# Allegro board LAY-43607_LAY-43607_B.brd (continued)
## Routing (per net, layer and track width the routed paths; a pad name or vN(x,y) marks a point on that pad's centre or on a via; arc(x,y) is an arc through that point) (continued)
AVDD_SRDS1_PLL1: length 0.6
  TOP w0.381: U14.AA11 v1(59.03,48.59)
  vias: v4(49.52,50.18) v4(50.28,49.93)
AVDD_SRDS1_PLL2: length 0.6
  TOP w0.381: U14.AB6 v1(58.22,52.6)
  vias: v4(49.64,54.63)
AVDD_SRDS2_PLL1: length 0.6
  TOP w0.381: U14.AB15 v1(59.02,45.39)
  vias: v4(46.34,47.77) v4(47.58,48.25) v4(49.79,47.9)
AVDD_SRDS2_PLL2: length 0.6
  TOP w0.137: U14.AA16 59.42,44.19
  TOP w0.381: 59.42,44.19 v1(59.02,43.79)
  vias: v4(46.19,43.48) v4(48.25,43.5) v4(49.01,43.45)
GND: length 689.8
  TOP w0.094: 36.21,73.66 36.62,74.07 36.8,74.07 37.2,73.67 U123.D9
  TOP w0.203: U38.2 75.88,109.42 ; U39.2 80.71,109.44
  TOP w0.254: U563.2 127.92,13.47 128.05,13.61 v2(128.1,13.61) ; v4(67.68,72.55) 68.1,72.97 U561.16 ; U540.4 84.78,99.74 v2(84.62,99.58) ; 110.88,92.27 U40.B3 U40.C3 ; J52.75 33.89,41.23 v4(33.84,41.18) ; J52.63 v4(30.89,41.18) ; U40.C3 U40.D3 110.87,93.07 ; U40.C3 110.86,92.67 ; U35.4 72.9,99.92 v2(72.55,99.57) ; R933.2 v4(69.07,85.49) ; U561.51 70.1,82.2 v4(70.21,82.31) ; v7(70.86,79.09) 70.86,79.99 71.6,80.73 U561.48 ; U550.C3 U550.B3 104.17,91.97 ; U550.C3 104.15,92.37 ; U550.C3 U550.D3 104.17,92.77 ; U540.5 84.78,98.33 84.59,98.52 v2(84.59,98.87) ; U37.4 77.19,98.3 v2(77.56,98.67) ; v2(127.24,55.26) 126.99,55.51 U558.7 ; U539.4 78.69,99.88 78.5,99.69 78.5,99.59 v2(78.41,99.51) ; U558.2 129.53,54.51 v2(129.4,54.37) 129.76,54.01 U558.1 ; U561.43 74.1,81.75 v4(74.55,82.2) ; v2(72.63,98.6) 72.9,98.33 U35.5 ; U539.5 78.69,98.24 78.42,98.51 v2(78.42,98.7) ; J52.69 v4(32.39,41.18) ; U561.45 v4(73.1,82.61) ; J52.57 v4(29.39,41.18) ; v7(70.8,76) 70.8,75.61 69.6,74.41 U561.19 ; J52.45 v4(26.39,41.18) ; U525.8 v4(92.16,85.76) ; U561.12 66.02,75.26 65.75,74.99 v4(64.92,74.99) ; J52.51 v4(27.89,41.16) ; R932.2 v4(69.96,85.44) ; C1546.2 v4(72.25,85.01) ; U1.14 v4(115.71,83.33) ; J52.18 v4(19.64,36.11) ; v2(77.51,99.56) 77.49,99.56 77.19,99.86 U37.5
  TOP w0.305: J52.39 v4(24.89,41.22) ; R841.1 v4(116.83,13.81) ; C1317.2 84.21,112.36 83.91,112.06 83.91,111.96 v4(83.79,111.84) 84.21,111.42 C1316.2 ; U551.3 v2(104.58,85.98) ; U548.2 v2(88.43,111.63) ; U536.3 121.3,10.63 v1(121.55,10.88) ; v2(81.49,98.59) 81.79,98.3 U36.5 ; U536.12 122.3,12.58 121.89,12.17 v1(121.55,12.17) ; U36.4 81.79,99.77 v2(81.56,99.54) ; v2(76.69,101.64) U37.6 ; U552.1 v2(97.43,99.93) ; J52.33 v4(23.39,41.2)
  TOP w0.381: U14.N26 65.82,36.2 v2(66.22,35.8) ; v2(74.22,56.6) U14.C1 ; U14.K15 68.22,45 v1(68.62,44.6) ; U14.C5 v1(74.62,53.8) U14.A4 ; U14.AG21 v2(55.02,40.6) 54.62,41 U14.AG20 U14.AH20 ; U14.AF10 55.42,49 v2(55.02,48.6) ; U14.J26 69.02,36.2 v2(69.42,35.8) ; U14.T11 v1(63.03,48.59) U14.U10 v1(62.23,49.39) 61.82,49.8 U14.V9 v1(61.43,50.19) ; U14.Y16 v1(59.82,44.59) ; v3(73.43,50.19) 73.03,49.8 U14.D9 ; v1(67.83,39.8) 68.22,40.2 U14.K21 ; U14.T23 63.42,38.6 v1(63.03,38.2) ; v2(59.83,35.8) 60.22,36.2 U14.Y26 ; U14.AB9 v2(59.02,49.4) ; U14.AD7 v1(56.62,51.8) ; U14.AA7 v2(59.02,51.8) ; U14.F3 v1(72.22,55.4) U14.E2 ; U14.H24 69.82,37.8 v2(70.22,37.4) ; v2(66.22,54.2) U14.N4 ; v2(72.63,39.8) 73.02,40.2 U14.D21 ; v2(56.62,37.4) 56.22,37.8 U14.AE24 ; C489.2 v4(121.54,19.94) ; v2(62.23,50.99) U14.U8 v1(63.03,50.19) U14.T9 63.42,49.79 v1(63.82,49.39) U14.R10 ; v2(62.22,39.8) 61.82,40.2 U14.V21 v2(61.42,39.79) U14.W22 ; U14.P13 v1(65.42,46.99) U14.N12 v1(66.22,47.79) U14.M11 v1(67.02,48.59) U14.L10 v2(67.82,49.39) ; U14.L20 67.42,41 v2(67.03,40.6) ; v2(75.99,40.2) U14.A21 ; U14.H14 69.83,45.8 v1(70.23,46.19) ; v1(62.23,38.2) 62.62,38.6 U14.U23 ; U14.AG26 54.62,36.2 v2(55.02,35.8) ; v2(59.82,38.19) U14.AA24 ; v2(63.03,35.8) 63.42,36.2 U14.T26 ; U14.R5 v1(63.83,53.39) ; U14.AH6 v2(53.42,51.8) ; v2(68.62,55.8) U14.K2 ; U14.AC5 v2(57.42,53.4) ; U14.V6 v1(61.43,52.59) ; v4(19.67,115.89) 19.97,115.59 C1151.2 ; U14.K6 68.62,52.6 v1(68.63,52.6) U14.J6 69.03,52.2 v2(69.43,51.79) 69.03,51.4 U14.J7 ; U14.AD21 v2(56.62,39.8) ; U14.M23 66.62,38.6 v1(67.02,38.2) ; U14.AH18 v2(53.42,43) U14.AH17 ; U14.AC18 v2(57.42,42.2) U14.AC19 ; U15.T1 88.79,6.11 88.69,6.21 88.1,6.21 v2(88.09,6.22) ; v2(56.63,54.19) U14.AD4 ; v1(69.43,48.59) 69.03,48.2 U14.J11 ; U14.H21 69.82,40.2 v2(69.43,39.8) ; v2(70.22,54.2) U14.H4 ; v3(73.43,47.79) 73.03,47.4 U14.D12 ; U14.P23 65.02,38.6 v1(65.42,38.2) ; v1(70.22,43.8) 69.82,44.2 U14.H16 ; v2(59.03,53.4) 59.42,53 U14.AA5 ; v2(74.23,39.8) 74.62,40.2 U14.B21 ; U14.P6 65.42,52.6 v1(65.43,52.6) ; U14.G26 70.62,36.2 v2(71.02,35.8) ; v2(59.82,45.39) U14.Y15 ; C1314.2 44.02,62.16 v4(43.71,61.85) ; v2(61.43,35.8) 61.82,36.2 U14.V26 ; U14.J23 69.02,38.6 v2(69.42,38.2) ; C1555.2 v4(118.21,28.5) ; U14.N20 65.82,41 v2(65.43,40.6) ; U14.R23 64.22,38.6 v1(63.83,38.2) ; v3(74.22,43.8) 74.62,44.2 U14.B16 ; U14.AC24 57.82,37.8 v2(58.22,37.4) ; v2(60.62,38.99) U14.Y23 ; U14.AE5 v2(55.82,53.4) ; v2(74.22,36.59) U14.B26 ; v2(72.62,35.8) 72.22,36.2 U14.E26 ; U14.N23 65.82,38.6 v1(66.22,38.2) ; FL8.2 v4(46.59,49.8) ; v2(55.82,36.59) U14.AF26 ; v1(60.63,42.2) 61.02,42.6 U14.W18 v1(61.43,43) 61.82,43.4 U14.V17 61.82,43.4 v1(62.23,43.8) 62.62,44.2 U14.U16 62.62,44.2 v1(63.03,44.6) 63.42,45 U14.T15 ; v1(68.62,46.99) U14.K13 v1(67.82,46.19) U14.L14 ; U14.AE7 v2(55.82,51.8) U14.AF7 ; U14.R12 v1(63.83,47.79) ; v2(70.22,53.4) U14.H5 ; v1(67.82,47.79) U14.L12 v1(67.02,46.99) U14.M13 v1(66.22,46.19) U14.N14 ; U14.AF8 v2(55.02,51) U14.AG8 v2(54.22,51) U14.AG7 ; U14.F16 71.42,44.19 v3(71.82,43.79) ; v2(74.23,41.4) 74.62,41.8 U14.B19 ; U14.AE17 v1(56.22,43.4) U14.AF18 v2(55.02,43) U14.AF17 U14.AF16 ; C492.2 v4(117.66,25.11) ; U14.AE14 v2(55.82,45.4) ; U14.AG14 v2(54.22,45.4) U14.AG15 ; v1(66.23,52.6) 66.22,52.6 U14.N6 ; v1(61.43,44.6) 61.82,45 U14.V15 ; U562.3 121.23,29.17 v4(121.22,29.17) ; U14.G9 70.63,49.8 v1(71.03,50.19) ; U14.AH9 v2(53.42,50.2) ; U14.AB26 58.62,36.2 v2(58.23,35.8) ; v1(60.62,40.6) U14.W20 v1(61.43,41.4) 61.82,41.8 U14.V19 61.82,41.8 v1(62.23,42.2) 62.62,42.6 U14.U18 62.62,42.6 v1(63.03,43) 63.42,43.4 U14.T17 v1(63.83,43.8) 64.22,44.2 U14.R16 ; U14.AG9 v2(54.22,50.2) ; U14.AH11 v2(53.42,47.8) U14.AH12 U14.AH13 U14.AG13 U14.AG12 v2(54.22,47.8) U14.AG11 ; v1(63.03,39.8) 63.42,40.2 U14.T21 v1(63.83,40.6) 64.22,41 U14.R20 ; v2(59.83,55.79) U14.Y2 ; v1(67.82,42.2) U14.K19 68.22,41.8 v2(67.83,41.4) ; U14.C2 v2(74.22,55.8) ; U14.B13 74.62,46.6 v3(74.22,46.2) ; v4(98.01,62.93) 98.01,62.94 98.39,63.32 U549.4 ; v2(59.83,51.8) 60.22,51.4 U14.Y7 ; v6(35.51,73.14) 35.83,73.46 36.01,73.46 36.21,73.66 ; v2(69.42,47.79) U14.J12 ; U14.AA19 v1(59.02,42.2) ; v2(75.96,55.4) U14.A2 ; v2(70.23,39.8) 70.62,40.2 U14.G21 ; v2(63.03,53.39) U14.T5 ; C1248.2 109.83,22.57 v3(109.03,21.77) 109.47,21.33 109.47,21.32 109.79,21 C1433.2 ; R662.2 C693.2 v5(43.39,87.27) ; v2(73.42,42.2) 73.02,42.6 U14.D18 ; U16.T1 v1(78.16,6.11) ; v2(56.63,35.8) 57.02,36.2 U14.AD26 ; v4(92.23,65.02) 91.84,65.41 U566.3 ; U14.C27 73.82,35.4 v1(74.22,35) ; U14.N8 v1(66.22,50.99) ; v2(73.43,39.8) 73.82,40.2 U14.C21 ; v1(67.83,52.6) 67.82,52.6 U14.L6 ; U14.AH5 v2(54.22,53.4) U14.AG5 ; U14.V23 61.82,38.6 v1(61.43,38.2) ; U14.AG6 v2(55.02,52.6) U14.AF6 ; U14.A3 v1(74.62,54.6) ; v1(67.02,50.19) U14.M9 v1(66.22,49.39) U14.N10 v1(65.42,48.59) U14.P11 ; U14.F7 71.43,51.4 v3(71.83,51.79) ; v1(68.62,49.4) 69.02,49 U14.J10 ; U14.P9 v1(65.42,50.19) ; v2(66.23,41.4) 66.62,41.8 U14.M19 v1(66.22,42.2) 65.82,42.6 U14.N18 v1(65.42,43) 65.02,43.4 U14.P17 ; v2(55.03,54.19) U14.AF4 ; U14.F4 71.77,53.45 U14.E5 U14.D4 v1(73.02,53.8) ; U14.AF9 v2(55.02,50.2) ; C284.2 v2(45.63,31.92) ; v2(59.02,50.2) U14.AA9 v1(59.82,49.39) U14.Y10 ; U14.U6 63.02,52.6 v1(63.03,52.6) U14.T6 ; v1(68.62,43) 68.22,43.4 U14.K17 v1(67.82,43.8) U14.L16 v1(67.02,44.6) 66.62,45 U14.M15 ; U14.AD12 v2(56.62,47.8) ; U14.Y14 v1(59.83,46.19) 59.82,46.19 U14.AA14 ; v1(60.62,47.79) U14.W12 61.02,47.39 v1(61.42,46.99) U14.V13 ; v2(71.83,39.8) 72.22,40.2 U14.E21 ; v2(56.63,55.79) U14.AD2 ; U14.AH14 v2(53.42,45.4) U14.AH15 ; U56.3 v4(121.07,26.41) ; U14.H18 69.82,42.6 v1(70.22,42.2) ; U14.AC10 v1(57.42,49.4) ; v1(59.02,47.8) U14.AA12 ; U530.3 100.01,87.72 100.6,87.14 v4(100.7,87.14) ; v2(64.96,30.22) 64.93,30.24 R141.1 ; U14.AC8 v2(58.22,50.2) ; v1(59.83,52.6) 60.22,52.2 U14.Y6 ; C1150.2 v5(42.78,110.76) ; U14.R14 v1(63.83,46.19) 63.42,46.6 U14.T13 v1(63.03,46.99) 62.62,47.4 U14.U12 v1(62.23,47.79) 61.82,48.2 U14.V11 v1(61.43,48.59) ; U14.U14 v1(62.22,46.19) ; U549.5 v4(101.09,63.32) ; U14.H17 69.82,43.4 v1(70.22,43) ; v2(54.22,56.6) U14.AG1 ; R185.2 v4(84.69,44.92) ; U14.AE9 v2(55.82,50.2) ; U14.U4 v1(62.23,54.19) ; U14.A5 76.11,53 v3(76.12,52.99) ; U14.M21 66.62,40.2 v2(66.23,39.8) ; U14.N2 v2(66.22,55.8) ; U14.B24 74.62,37.8 v2(75.02,37.4) ; v2(71.82,42.2) U14.F18 ; U14.AB14 v1(59.02,46.19) ; v2(71.03,49.39) 70.63,49 U14.G10 ; v3(75.03,49.39) 74.63,49 U14.B10 ; U14.H15 69.82,45 v1(70.22,44.6) ; v2(61.43,54.19) U14.V4 ; v5(129.22,41.93) R64.2 ; U14.AF15 v2(55.02,45.4) ; v2(63.03,54.19) U14.T4 ; R177.2 v4(85.46,44.79) ; U14.AC6 v1(57.42,52.6) ; C282.2 v2(45.6,27.17) ; U14.AG18 v2(54.22,43) U14.AG17 ; U14.Y21 v2(59.82,39.8) ; U14.AA18 v1(59.02,43) U14.AB17 ; U14.AB7 v2(58.22,51.8) ; v2(58.23,55.79) U14.AB2 ; v2(67.82,35.8) U14.L26 ; U14.P15 65.02,45 v1(65.42,44.6) U14.N16 65.82,44.2 v1(66.22,43.8) U14.M17 v1(67.02,43) U14.L18 ; U14.H3 v2(70.22,55) U14.G2 U14.G1 ; v2(53.43,55.79) U14.AH2 ; U14.Y13 v1(59.83,46.99) ; v2(63.83,35.8) 64.22,36.2 U14.R26 ; C1142.2 v5(65.82,115.46) ; v2(59.83,53.4) 60.22,53 U14.Y5 ; U14.AC11 v2(57.42,48.6) ; U14.L23 v1(67.82,38.2) ; v2(68.62,54.2) U14.K4 ; v2(63.82,55) U14.T2 ; U14.AA17 v1(59.82,43.79) ; U14.B7 74.63,51.4 v3(75.03,51.79) ; v1(58.22,47.8) U14.AB12 ; U14.AH21 v2(53.24,40.2) ; v1(64.63,41.4) 65.02,41.8 U14.P19 ; v1(71.03,48.59) 70.63,48.2 U14.G11 ; U14.AD14 v1(56.62,45.4) ; U14.R8 v1(63.83,50.99) ; v1(67.03,52.6) 67.02,52.6 U14.M6 ; U14.AC15 v2(58.22,45.4) ; v1(69.43,50.19) 69.03,49.8 U14.J9 ; U14.AA21 v1(59.02,39.8) ; U14.AD9 v2(56.62,50.2) ; U14.D24 73.02,37.8 v2(73.42,37.4) ; U14.AG24 54.62,37.8 v2(54.23,37.4) ; U14.AF21 v2(55.02,39.8) ; U14.AH7 v2(53.42,51) U14.AH8 ; U14.F14 71.43,45.8 v1(71.83,46.19) ; U14.D15 73.02,44.99 v3(73.42,44.59) ; U14.AD5 v2(56.62,53.4) ; U14.AC21 v1(58.22,40.6) ; U14.R18 64.22,42.6 v1(63.83,42.2) U14.T19 v1(63.03,41.4) 62.62,41 U14.U20 62.62,41 v1(62.23,40.6) ; U14.J21 69.02,40.2 v2(68.63,39.8) ; U14.AB20 v1(59.02,41.4) ; v2(61.43,55.79) U14.V2 ; v3(73.43,51.79) 73.03,51.4 U14.D7 ; U14.Y9 U14.Y8 60.22,50.6 v2(59.83,51) ; v2(71.82,37.4) U14.F24 ; Q4.1 v4(94.74,48.65) ; U14.J8 69.03,50.6 v2(68.63,50.19) ; U14.AE12 v2(55.82,47.8) ; U14.AF19 v2(55.02,41.4) ; U14.AF11 v2(55.02,47.8) ; U14.AE21 v2(55.82,39.8) ; C1315.2 v4(100.26,66.81) ; v2(59.03,54.19) U14.AA4
  TOP w0.406: U557.E5 v3(118.55,43.76) ; U557.F5 v3(117.75,43.76) ; U557.G2 v3(116.95,46.96) ; U557.G5 v3(116.95,43.76) ; U557.F1 v3(117.75,47.76) ; U557.G6 v3(116.95,42.96) ; U557.F2 v3(117.75,46.96) ; U557.G1 v3(116.95,47.76) ; U557.E2 v3(118.55,46.96) ; U557.E1 v3(118.55,47.76) ; U557.E6 v3(118.55,42.96) ; U557.F6 v3(117.75,42.96)
  TOP w0.432: U16.E8 v1(84.16,15.31) ; U18.C9 v1(50.52,16.91) ; U16.H9 v1(84.96,12.91) ; U17.B2 v1(55.6,17.71) ; U17.N1 v2(54.22,8.51) ; U16.D8 v2(84.16,16.11) ; U18.A2 v1(44.12,18.51) ; U16.N9 85.09,8.51 85.12,8.54 v2(85.12,8.54) ; U565.G8 v1(72.68,13.71) ; U565.F1 v1(66.28,14.51) ; U17.A8 v1(61.21,18.51) ; U16.A8 v1(84.16,18.51) ; U18.B2 v1(44.12,17.71) ; U15.G8 v2(95.64,12.91) ; U18.D8 v2(49.72,16.11) ; U15.A8 v1(95.64,18.51) ; U565.A2 v1(67.08,18.51) ; U18.G8 v1(49.72,13.71) ; U16.F1 v1(77.76,14.51) ; U15.E3 v2(90.84,15.31) ; U17.E9 v2(62,15.31) ; U17.T1 v1(54.47,6.11) ; U15.D2 v2(90.04,16.11) ; U17.A2 v1(55.6,18.51) ; U565.C9 v1(73.48,16.91) ; U15.H1 v2(89.24,12.91) ; U17.G8 v1(61.2,13.71) ; U17.H1 v1(54.8,12.91) ; U15.H9 96.55,12.51 v1(96.66,12.62) ; U17.E1 v2(54.8,15.31) ; U18.E3 v2(44.92,15.31) ; U565.H9 v1(73.48,12.91) ; U565.A8 v1(72.68,18.51) ; U17.D8 v1(61.2,16.11) ; U15.F1 v1(89.24,14.51) ; U16.A2 v2(78.56,18.51) ; U17.F1 v1(54.8,14.51) ; U565.E3 v2(67.88,14.51) ; U18.D2 v2(44.12,16.11) ; U17.E3 v2(56.4,15.31) ; U16.E1 v1(77.76,15.31) ; U16.E3 v2(79.36,14.51) ; U565.N9 73.61,8.51 73.64,8.54 v2(73.64,8.54) ; U15.A2 v1(90.04,18.51) ; U16.C9 v1(84.96,16.91) ; U17.D2 v2(55.6,16.11) ; U16.G8 v1(84.16,13.71) ; U15.E1 v1(89.24,15.31) ; U565.D8 v2(72.68,16.11) ; U565.H1 v1(66.28,12.91) ; U18.E9 v1(50.52,15.31) ; U16.D2 v2(78.56,16.11) ; U16.H1 v1(77.76,12.91) ; U15.C9 v1(96.66,16.51) ; U565.B2 v2(67.08,17.71) ; U15.E8 v1(95.24,15.71) ; U565.E8 v1(72.68,15.31) ; U18.H9 v1(50.52,12.91) ; U18.E8 v1(49.72,15.31) ; U17.E8 v1(61.2,15.31) ; U565.D2 v2(67.08,16.11) ; U15.E9 v1(96.66,14.91) ; U18.E1 v2(43.32,15.31) ; U565.E9 v1(73.48,15.31) ; U17.H9 v2(62,12.91) ; U17.C9 v1(62,16.91) ; U565.E1 v1(66.28,15.31) ; U16.E9 v1(84.96,15.31) ; U18.A8 v1(49.72,18.51) ; U16.B2 v2(78.56,17.71) ; U15.B2 v2(90.04,17.71)
  TOP w0.508: 80.71,109.44 v2(80.71,109.06) ; R943.2 v4(64.63,74.34) ; v4(79.9,59.62) R883.2 ; v4(103.41,90.06) 103.53,90.06 103.71,89.88 C1320.2 ; R277.1 20.97,69.93 21.43,70.39 v4(21.43,70.51) ; C169.2 v4(84.54,57.86) ; J58.5 120.54,8.18 v4(120.76,8.4) ; C1139.2 v4(46.47,89.48) ; U28.5 v2(99.37,56.83) ; J67.8 22.18,104.61 v5(22.2,104.63) ; C172.2 v5(85.94,57.81) ; J67.7 v5(16.78,104.61) ; C1141.2 v5(42.78,110.76) ; U538.4 v5(110.22,65.12) ; 75.88,109.42 v2(75.88,108.96) ; R945.1 v4(37.11,65.28) ; v1(113.45,25.39) 113.39,25.44 U532.10 ; 26.02,72.66 v5(25.12,72.66) ; 22.34,88.92 22.17,88.92 v4(21.79,89.3) ; C498.2 48.21,64.74 v4(48.62,65.15) ; R902.2 v5(114.96,74.72) ; v5(51.64,63.16) 51.67,63.12 R823.2 ; v4(45.71,53.04) 46.03,52.72 C275.2 ; C302.2 v2(46.57,56.91) ; v4(21.8,60.45) R776.1 21.77,61.78 R775.1 ; v5(131.9,34.75) SW6.1 v5(131.9,38.78) ; J15.5 v4(28.37,82.82) ; J15.3 v4(28.27,81.55) ; R192.2 v5(92.29,46.98) ; v5(110.17,96.33) 111.54,96.33 L11.2 ; R887.2 124.65,41.98 C125.2 124.45,41.46 v4(124.24,41.25) ; C277.2 v5(43.8,55.54) ; C1140.2 v4(63.92,89.63) ; 26.02,73.93 v5(25.17,73.93) ; C1552.2 C1553.2 v5(68.44,69.79) 68.49,69.74 R935.1 ; J67.13 v5(14.54,95.85) ; R930.2 C1554.2 ; C1157.2 v4(36.82,89.04) ; U524.1 101.05,83.68 v4(101.33,83.96) ; v4(34.73,79.85) 34.48,80.1 FL19.2 31.46,80.1 v4(31.09,80.47) ; J67.14 v5(21.73,96.99)
  TOP w0.889: 129.78,79.22 J75.2 ; J75.2 130.71,80.15 ; J75.2 129.78,81.08 ; BH9.1 28.06,9.03 ; BH9.1 24.64,12.44 ; BH9.1 21.22,9.03
  L2_GND w0.889: 91.06,96.8 J57.8 ; J57.8 93.09,96.8 ; J57.8 92.08,97.82 ; J57.8 92.08,95.79 ; J56.8 69.22,97.82 ; J56.8 68.2,96.8 ; J56.8 69.22,95.79 ; J56.8 70.23,96.8 ; 48.58,96.63 P1.20 ; P1.20 48.58,98.36 ; P1.20 47.71,97.49 ; P2.20 25.29,98.35 ; P2.20 24.42,97.49 ; P2.20 25.29,96.62 ; 128.53,50.69 TP94.1 ; TP94.1 131.18,50.69 ; TP94.1 129.86,52.01 ; TP94.1 129.86,49.37 ; J63.2 107.88,74.43 ; J63.2 106.95,73.5 ; J63.2 106.02,74.43 ; J63.2 106.95,75.36 ; BT3.3 17.55,63.45 ; BT3.3 18.54,62.45 ; BT3.3 17.55,61.46 ; BT3.3 16.56,62.45 ; J60.1 129.8,34.09 ; J60.1 128.88,33.16 ; J60.1 130.73,33.16 ; J60.1 129.8,32.24 ; 75.64,88.79 J66.5 ; J66.5 76.57,87.86 ; J66.5 76.57,89.72 ; J66.5 77.49,88.79 ; P1.1 60.58,108.77 ; P1.1 61.44,107.9 ; P1.1 60.58,107.04 ; 24.38,17.78 BH10.1 ; BH10.1 27.8,21.2 ; BH10.1 20.97,21.2 ; BH10.1 24.38,24.62 ; 129.75,16.01 J73.4 ; J73.4 128.83,16.93 ; J73.4 129.75,17.86 ; J73.4 130.68,16.93 ; P2.1 38.15,107.9 ; P2.1 37.29,108.76 ; P2.1 37.29,107.03 ; J70.4 101.73,107.27 ; J70.4 100.17,107.27 ; J70.4 100.95,108.04 ; J70.16 105.23,102.57 ; J70.16 104.45,101.79 ; J70.16 103.67,102.57 ; J70.16 104.45,103.34 ; J75.2 129.78,81.08 ; J75.2 129.78,79.22 ; J75.2 128.86,80.15 ; J75.2 130.71,80.15 ; 106.02,71 J64.2 ; J64.2 107.88,71 ; J64.2 106.95,71.93 ; J64.2 106.95,70.07 ; 21.22,9.03 BH9.1 ; BH9.1 28.06,9.03 ; BH9.1 24.64,12.44 ; BH9.1 24.64,5.61 ; TP95.1 89.83,82.19 ; TP95.1 88.5,80.86 ; TP95.1 88.5,83.51 ; TP95.1 87.18,82.19 ; J70.7 105.23,105.77 ; J70.7 104.45,106.54 ; J70.7 103.67,105.77 ; J70.7 104.45,104.99 ; 101.73,104.07 J70.13 100.17,104.07 ; J65.2 107.88,67.57 ; J65.2 106.95,66.64 ; J65.2 106.95,68.5 ; J65.2 106.02,67.57 ; 106.08,60.09 J13.1 ; J13.1 107.5,60.09 ; J13.1 106.79,60.8
  L5_PWR w0.889: 21.22,9.03 BH9.1 ; BH9.1 28.06,9.03 ; BH9.1 24.64,5.61 ; BH9.1 24.64,12.44 ; 104.45,101.79 J70.16 ; J70.16 103.67,102.57 ; J70.16 105.23,102.57 ; J70.16 104.45,103.34 ; TP95.1 88.5,83.51 ; TP95.1 88.5,80.86 ; TP95.1 87.18,82.19 ; TP95.1 89.83,82.19 ; J70.4 101.73,107.27 ; J70.4 100.17,107.27 ; J70.4 100.95,108.04 ; 24.38,17.78 BH10.1 ; BH10.1 20.97,21.2 ; BH10.1 24.38,24.62 ; BH10.1 27.8,21.2 ; 104.45,104.99 J70.7 ; J70.7 105.23,105.77 ; J70.7 103.67,105.77 ; J70.7 104.45,106.54 ; 101.73,104.07 J70.13 100.17,104.07
  BOTTOM w0.254: v2(100.65,96.93) U553.8 U553.3 ; v2(18.15,108.65) 18.13,108.67 U543.2 ; U544.2 18.08,98.51 v2(18.18,98.41) ; U564.2 v4(127.06,23.15) ; U545.2 18.19,93.44 v2(18.29,93.34) ; v2(96.17,97.05) U44.8 U44.3 v2(96.17,94.46) ; J46.18 v4(29.38,48.18)
  BOTTOM w0.279: J46.7 v2(32.13,55.79) ; J46.33 v2(25.63,55.79) ; J46.51 v2(21.13,55.71) ; J46.1 v2(33.63,55.8) ; J46.39 v2(24.13,53.5) ; J46.45 v2(22.63,53.5)
  BOTTOM w0.305: v2(78.41,99.51) 78.73,99.51 78.8,99.59 C1307.2 ; v2(72.55,99.57) 72.73,99.57 72.73,99.56 C450.2 ; v2(72.63,98.6) 72.79,98.44 C449.2 ; v2(84.62,99.58) 84.75,99.71 C1309.2 ; C451.2 81.57,98.52 v2(81.49,98.59) ; J46.75 15.13,55.68 v4(14.95,55.87) ; C1306.2 78.6,98.52 v2(78.42,98.7) ; v2(77.51,99.56) C454.2 ; C452.2 81.6,99.59 v2(81.56,99.54) ; v2(84.59,98.87) 84.59,98.77 84.9,98.47 C1308.2 ; R880.2 104,86.57 v2(104.58,85.98) ; v4(16.63,55.85) J46.69 ; v4(18.13,55.85) J46.63 ; v4(19.63,55.85) J46.57
  BOTTOM w0.381: C1406.2 v1(87.28,9.54) ; C1394.2 92.52,17.03 v2(92.97,16.58) ; v5(47.99,74.62) 47.17,74.62 C1016.2 C1017.2 ; C1388.2 95.16,15.62 v1(95.24,15.71) ; C1557.2 65.95,6.22 66.03,6.14 66.65,6.14 v1(66.68,6.11) ; v1(43.72,6.11) 43.61,6.22 C1365.2 ; C1351.2 61.07,13.47 C374.2 ; v4(31.41,69.56) 31.96,69.01 FL29.2 31.96,65.94 31.58,65.56 28.33,65.56 ; v4(45.16,38.24) R102.2 ; U533.3 v4(121.22,29.17) ; U522.C5 v3(106.68,23.42) ; C1251.2 v4(108.62,30.78) ; U534.3 119.62,16.72 v4(119.46,16.87) ; C1323.2 107.83,97.02 v5(108.32,96.54) ; U522.F7 v3(109.03,21.77) ; v2(85.97,5.94) 85.42,5.94 C1425.2 ; C1297.2 v4(124.89,27.87) ; C487.2 v4(124.21,23.64) ; C1421.2 77.43,6.22 77.51,6.14 78.13,6.14 v1(78.16,6.11) ; C453.2 77.38,98.49 v2(77.56,98.67) ; v1(61.6,9.31) 61.72,9.42 C1396.2 ; C1018.2 v5(47.98,73.02) ; v4(87.28,40.44) R817.2 R818.2 ; v2(73.72,5.34) 73.72,5.38 C1566.2 ; v1(43.72,14.11) 43.29,14.11 42.99,13.81 C1362.2 ; C247.2 59.78,44.54 arc(59.84,44.55) C262.2 ; C333.2 C332.2 ; C519.2 v1(54.12,16.11) ; C243.2 C240.2 v4(80.83,51.18) ; C230.2 v4(80.84,48.84) ; C1402.2 v2(88.09,6.22) ; C1562.2 72.1,18.51 71.83,18.24 R84.1 ; C157.2 67.82,49.4 v2(67.82,49.39) ; U114.3 v4(121.07,26.41) ; C310.2 v4(75.04,33.49) ; C1395.2 U15.G8 v2(95.64,12.91) ; v4(103.17,64.52) 102.87,64.82 C1318.2 ; C306.2 v4(67.04,32.9) ; v2(47.39,12.63) 47.91,12.12 48.18,12.12 48.59,11.7 C1376.2 ; v4(21.43,70.51) 21.47,70.51 21.96,70.02 C1273.2 FL28.2 22.02,67.08 C1272.2 21.7,66.91 ; U58.3 v4(19.46,56.64) ; C367.2 v4(61.58,4.57) ; v2(65.43,40.6) 65.31,40.48 R964.2 ; C493.2 v4(15.38,59.79) ; U546.3 v4(45.9,60.64) ; C235.2 v4(80.72,44.1) ; C905.2 v4(125.07,25.1) ; v1(84.56,10.91) 84.63,10.98 C1417.2 ; C1391.2 88.25,13.66 v7(87.67,13.07) ; v4(58.91,33.49) 58.91,33.67 59.07,33.82 C320.2 ; C303.2 C316.2 ; C308.2 v4(70.22,33.55) ; C307.2 v4(71.82,33.55) ; v1(73.08,10.91) 73.15,10.98 C1570.2 ; U522.K8 v3(113.05,20.97) ; C324.2 v4(54.21,33.49) ; C305.2 v4(53.33,33.49) ; C311.2 v4(57.39,33.49) ; U522.K3 v1(113.45,25.39) ; C322.2 v4(55.87,33.49) ; U55.2 v4(121.02,22.98) ; C304.2 v4(65.42,33.55) ; C245.2 v4(86.48,38.37) ; C297.2 79.09,39.92 78.73,40.28 v4(78.66,40.28) ; C321.2 v4(60.69,33.49) ; C246.2 v4(88.08,38.37) ; C497.2 v4(14.65,61.38) ; C1319.2 v4(97.99,64.82) ; C284.2 v2(45.63,31.92) ; U535.3 v4(102.37,69.6) ; U547.3 v4(99.36,68.66) ; U60.3 v4(19.57,59.26) ; v4(43.93,38.63) FL7.2 43.93,40.51 44.3,40.88 v4(44.49,40.88) ; C323.2 v4(62.23,33.55)
  BOTTOM w0.508: C161.2 C330.2 56.27,60.78 v5(56.27,61.71) ; R412.2 92.71,65.5 v4(92.23,65.02) ; v5(85.89,91.84) 86.27,92.22 C1259.2 ; C231.2 C230.2 ; C388.2 18.89,112.79 18.38,113.3 v4(18.38,113.46) ; 91.17,32.91 v5(92.11,32.91) ; C300.2 47,56.89 46.98,56.91 v2(46.57,56.91) ; v4(44.53,65.32) 44.73,65.52 U62.3 ; C1466.2 127.85,11.18 v4(128.17,11.5) ; C1329.2 90.74,98.14 J57.8 ; v5(85.94,57.81) 85.94,57.24 C171.2 ; U523.8 16.55,81.55 16.2,81.2 v4(16.18,81.2) ; U523.2 v5(18.83,73.93) ; R100.2 v5(90.59,38.83) ; v4(84.54,57.86) 84.72,57.68 C173.2 ; FL30.2 22.02,60.67 v4(21.8,60.45) ; C1295.2 106.36,31.84 C1296.2 ; C1382.2 v1(41.87,10.3) ; C1465.2 v4(128.5,24.99) ; R882.2 103.7,90.19 103.58,90.06 v4(103.41,90.06) ; U527.3 v5(91.4,88.64) ; R793.2 v4(100.7,87.14) ; C369.2 v4(54.52,19.45) ; C1334.2 128.13,55.26 v2(127.24,55.26) ; R188.1 v4(20.51,86.86) ; v2(41.03,89.77) 41.5,89.3 FL22.2 C1103.2 43.82,89.3 44.53,88.59 C1104.2 45.61,88.59 46.47,89.45 v4(46.47,89.48) ; U42.1 v4(101.48,111.18) ; v4(120.76,8.4) 119.98,9.18 U537.1 ; C1324.2 v5(103.44,96.05) ; C1305.2 v5(103.44,63.17) ; v4(82.33,55.72) 82.61,56 R473.2 ; v4(94.85,61.47) C1256.2 ; C254.2 v4(45.83,41.08) ; C1003.2 36.85,80.8 ; C729.2 v4(42.89,91.51)
  BOTTOM w0.889: BH10.1 27.8,21.2 ; BH10.1 24.38,17.78 ; BH10.1 20.97,21.2 ; BH10.1 24.38,24.62 ; 68.46,96.04 J56.8 68.2,96.8 ; J75.2 129.78,81.08 ; J75.2 129.78,79.22 ; J75.2 130.71,80.15
  vias: v1(19.54,111.06) v1(19.54,108.43) v1(19.54,105.8) v1(41.51,12.59) v1(42.42,18.82) v1(42.64,16.91) v1(42.64,16.11) v1(43.72,12.51) v1(43.72,10.91) v1(43.72,8.51) v1(50.12,10.91) v1(50.12,9.31) v1(50.12,8.51) v1(50.84,11.7) v1(50.82,10.1) v1(51.29,12.88) v1(51.47,6.11) v1(52.31,15.13) v1(52.84,10.69) v1(53.73,10.69) v1(54.52,11.71) v1(55.2,10.91) v1(56.22,41) v1(57.02,43.4) v1(57.02,41) v1(57.82,44.2) v1(61.6,10.91) v1(61.6,8.51) v1(62.43,11.7) v1(66.68,10.91) v1(66.68,8.51) v1(68.7,17.72) v1(69.43,50.99) v1(72.22,56.2) v1(73.03,54.6) v1(73.08,9.31) v1(78.16,10.91) v1(78.16,8.51) v1(80.19,17.72) v1(84.56,9.31) v1(86.72,15.17) v1(88.15,11.7) v1(88.25,10.56) v1(89.64,10.91) v1(89.64,8.51) v1(96.04,10.91) v1(96.04,9.31) v1(96.04,8.51) v1(96.76,11.03) v1(96.73,6.11) v1(97.95,15.51) v1(120.88,11.52) v1(121.55,11.52) v1(122.2,11.49) v2(22.49,56.27) v2(23.08,44.79) v2(24.28,56.27) v2(25.2,44.79) v2(42.13,68.72) v2(44.4,68.72) v2(89.89,59.29) v2(99.05,92.22) v2(100.62,92.17) v2(102.16,92.17) v4(14.02,43.54) v4(14.59,30.8) v4(14.59,28.26) v4(14.59,25.72) v4(14.59,23.18) v4(14.59,20.64) v4(14.59,18.1) v4(14.59,15.56) v4(14.59,13.02) v4(14.59,10.48) v4(14.59,7.94) v4(15.64,44.02) v4(16.84,43.64) v4(17.68,43.89) v4(19.06,30.78) v4(19.06,28.24) v4(19.06,25.7) v4(19.06,23.16) v4(19.06,20.62) v4(19.06,18.08) v4(19.06,15.54) v4(19.06,13) v4(19.06,10.46) v4(19.06,7.92) v4(28.99,30.78) v4(28.99,28.24) v4(28.99,25.7) v4(28.99,23.16) v4(28.99,18.08) v4(28.99,15.54) v4(28.99,13) v4(29.36,10.44) v4(29.54,8.05) v4(29.64,48.86) v4(29.67,21.05) v4(29.72,50.27) v4(30.24,49.2) v4(30.67,85.56) v4(30.64,83.53) v4(30.67,82.62) v4(30.69,84.45) v4(30.69,81.65) v4(30.74,77.44) v4(31.25,79.32) v4(33.44,30.29) v4(33.56,28.26) v4(33.56,25.72) v4(33.56,23.18) v4(33.56,20.64) v4(33.56,18.1) v4(33.56,15.56) v4(33.56,13.02) v4(33.56,10.48) v4(33.56,7.94) v4(33.82,45.33) v4(34.69,45.34) v4(35.31,18.18) v4(35.29,17.11) v4(36.23,32.99) v4(36.18,23.39) v4(36.19,18.89) v4(36.31,25.93) v4(37.42,33.06) v4(37.7,23.39) v4(37.83,25.93) v4(37.88,38.4) v4(38.42,33.01) v4(38.99,38.24) v4(39.3,33.34) v4(49.72,45.33) v4(49.85,46.22) v4(52.38,52.87) v4(52.82,52.21) v4(53.06,84.26) v4(53.06,83.54) v4(53.36,86.82) v4(53.36,86.11) v4(53.33,81.17) v4(53.33,79.9) v4(53.33,78.38) v4(53.33,77.11) v4(55.36,85.74) v4(55.36,84.73) v4(55.36,83.46) v4(55.36,82.19) v4(55.36,80.92) v4(55.36,79.65) v4(55.36,78.38) v4(55.36,76.85) v4(55.36,75.33) v4(55.36,74.06) v4(55.36,72.79) v4(73.54,68.07) v4(74.31,68.54) v4(85.53,77.05) v4(85.71,81.68) v4(85.79,74.24) v4(85.83,72.66) v4(85.94,80.47) v4(85.94,79.76) v4(85.94,79.05) v4(85.91,75.67) v4(87.29,49.72) v4(87.31,48.84) v4(87.28,47.9) v4(88.2,49.67) v4(89.33,49.69) v4(90.21,49.62) v4(91.26,49.63) v4(91.21,48.57) v4(91.21,47.69) v4(91.91,47.99) v4(101.25,81.22) v4(101.25,80.38) v4(101.79,73.65) v4(101.94,72.97) v4(102.52,73.42) v4(103.97,76.83) v4(106.92,30.57) v4(107,31.34) v4(109.56,8.81) v4(109.56,7.33) v4(109.64,13.99) v4(109.64,12.74) v4(109.59,11.7) v4(109.61,10.08) v4(114.92,12.97) v4(116.32,11.83) v4(119.59,19.96) v4(124.68,11.21) v4(125.56,11.68) v4(126.56,11.69) v5(41.67,112.87) v5(41.72,111.93) v5(42.66,112.84) v5(42.68,111.96) v5(43.62,112.84) v5(43.65,111.98) v5(66.13,93.03) v5(66.36,96.59) v5(66.41,95.04) v5(67.09,93.03) v5(67.4,96.56) v5(72.47,65.61) v5(73.45,65.61) v5(76.39,119.12) v5(76.44,116.22) v5(77.3,119.17) v5(84.49,114.9) v5(85.58,114.85) v5(86.57,114.85) v5(87.62,114.83) v5(96.61,32.57) v5(96.81,115.36) v5(97.8,115.33) v5(98.82,115.28) v5(99.21,105.88) v5(100.97,32.71) v5(101.2,25.29) v5(101.47,27.34) v5(101.43,26.12) v5(106.61,98.06) v5(108.21,95.72) v5(108.96,79.65) v5(109.45,102.05) v5(109.46,80.41) v5(109.46,78.76) v5(109.65,105.73) v5(110.22,78) v5(110.35,81.32) v5(110.48,54.75) v5(110.6,49.67) v5(110.98,35.69) v5(110.98,34.89) v5(111.24,82.57) v5(111.62,55.01) v5(111.62,53.99) v5(111.67,40.66) v5(111.75,78) v5(111.75,49.67) v5(111.87,64.28) v5(111.87,62.88) v5(112.13,36.14) v5(112.13,35.2) v5(112.63,64.91) v5(112.66,55.01) v5(112.66,53.99) v5(112.76,89.04) v5(112.76,88.03) v5(112.76,86.89) v5(112.71,40.66) v5(112.79,49.67) v5(112.89,85.87) v5(113.16,69.29) v5(113.17,36.21) v5(113.17,35.2) v5(113.21,98.32) v5(113.48,70.27) v5(113.65,53.74) v5(113.65,52.72) v5(113.65,51.58) v5(113.65,50.44) v5(113.78,64.91) v5(113.9,40.28) v5(113.9,39.26) v5(113.9,38.12) v5(113.9,36.97) v5(114.5,70.32) v5(114.82,64.91) v5(114.92,96) v5(115.04,96.78) v5(115.05,53.74) v5(115.05,52.72) v5(115.05,51.58) v5(115.05,50.44) v5(115.32,69.98) v5(115.3,40.28) v5(115.3,39.26) v5(115.3,38.12) v5(115.28,37.08) v5(116.13,48.64) v5(116.46,51.79) v5(116.57,34.43) v5(116.7,40.28) v5(116.7,39.26) v5(116.7,38.12) v5(116.7,37.23) v5(117.17,48.98) v5(117.61,34.43) v5(117.74,37.23) v5(118.6,84.35) v5(118.98,76.98) v5(118.98,37.23) v5(118.98,34.43) v5(119.11,33.42) v5(119.87,80.92) v5(119.87,76.98) v5(120.05,83.29) v5(120.79,76.98) v5(120.89,80.92) v5(122.79,76.09) v5(122.84,71.32) v5(123.23,64.67) v5(123.18,33.93) v5(123.18,32.91) v5(123.33,74.9) v5(123.89,71.3) v5(124.34,74.85) v5(124.63,64.67) v5(124.7,70.88) v5(124.88,96.38) v5(125.36,75.96) v5(125.33,75.07) v5(125.56,91.69) v5(125.61,70.88) v5(125.84,64.66) v5(125.84,63.64) v5(125.84,62.37) v5(126.12,98.21) v5(126.12,93.46) v5(127.21,94.3) v5(127.21,92.65) v5(127.62,64.66) v5(127.62,63.64) v5(127.62,62.37) v5(128.28,98.21) v5(129.14,76.09) v5(129.14,64.66) v5(129.14,63.64) v5(129.14,62.37) v5(129.27,75.2) v5(129.37,94.3) v5(129.37,92.65) v5(129.91,81.93) v5(130.16,78.38) v5(130.52,98.16) v5(130.85,94.3) v5(130.85,92.6) v5(130.82,89.83) v5(130.82,88.13) v5(130.8,85.82) v5(130.8,84.12) v5(131.05,81.93) v5(131.05,78.38) v6(35.35,71.84) v6(35.39,70.89) v6(36.76,70.57) v6(40.54,70.47) v6(42.33,70.39) v7(22.06,8.38) v7(22.22,9.91) v7(22.38,22.64) v7(22.61,7.25) v7(22.71,19.22) v7(22.96,10.96) v7(23.47,23.57) v7(23.78,6.49) v7(24.55,18.68) v7(24.57,11.61) v7(25.1,23.58) v7(25.46,6.61) v7(25.97,65.22) v7(25.98,19.21) v7(26.36,22.86) v7(26.43,10.89) v7(26.48,7.17) v7(26.83,65.97) v7(26.85,65.2) v7(26.82,64.27) v7(26.83,20.35) v7(26.95,21.67) v7(27.74,65.18) v7(40.41,76.09) v7(41.19,76.07) v7(41.96,76.78) v7(41.93,75.18) v7(41.91,74.43) v7(41.98,77.53) v7(41.98,76.06) v7(42.84,76.04) v7(43.62,76.02) v7(53.23,13.1) v7(62.72,62.5) v7(63.74,8.26) v7(64.02,15.17) v7(64.83,13.1) v7(65.14,11.24) v7(65.26,62.5) v7(65.38,18.82) v7(65.42,16.16) v7(65.54,8.27) v7(68.18,62.5) v7(69.12,76.02) v7(69.26,78.32) v7(69.25,77.53) v7(69.9,76.02) v7(70.09,79.08) v7(70.08,78.35) v7(70.1,77.62) v7(70.84,78.35) v7(70.86,77.62) v7(70.83,76.71) v7(71.53,76.68) v7(71.63,79.09) v7(71.6,78.35) v7(71.63,77.62) v7(72.37,78.35) v7(72.36,76.71) v7(72.39,79.09) v7(72.39,77.62) v7(75.35,15.12) v7(75.3,8.26) v7(76.29,13.2) v7(76.63,11.29) v7(76.86,18.82) v7(76.9,16.16) v7(77,8.27) v7(88.22,18.86) v7(88.25,16.18) v7(96.71,31.61) v7(98.36,31.61) v7(99.76,31.61) v7(124.26,10.6) v7(125.33,13.61)
GND_EARTH: length 130.5
  TOP w0.508: 114.29,3.83 114.29,3.82 J58.S3 113.42,1.95 113.4,1.92
  TOP w0.889: 61.75,117.73 P1.S3 ; P1.S3 62.97,118.95 ; P1.S3 64.19,117.73 ; J70.S1 111.02,110.91 ; J70.S1 112.66,109.27 ; J70.S1 111.02,107.63 ; 62.97,100.15 P1.S1 ; P1.S1 64.19,101.37 ; P1.S1 62.97,102.59 ; P1.S4 47.4,117.73 ; P1.S4 46.18,116.51 ; P1.S4 46.18,118.95 ; P1.S4 44.96,117.73 ; 22.89,100.15 P2.S2 22.89,102.59 ; P2.S3 40.9,117.73 ; P2.S3 39.68,116.51 ; P2.S3 38.46,117.73 ; P2.S3 39.68,118.95 ; 97.88,107.63 J70.S4 ; J70.S4 96.24,109.27 ; J70.S4 97.88,110.91 ; 19.1,117.81 BH5.1 15.83,114.54 ; 114.29,7.17 J58.S1 113.53,5.95 ; 96.24,103.59 J70.S3 ; J70.S3 97.88,101.95 ; J70.S3 97.88,105.23 ; 22.89,116.51 P2.S4 ; P2.S4 21.67,117.73 ; P2.S4 24.11,117.73 ; J70.S2 112.66,103.59 ; J70.S2 111.02,101.95 ; J70.S2 111.02,105.23
  L3_INT_1 w0.889: 122.96,88.03 BH8.1 ; BH8.1 129.49,88.03 ; BH8.1 126.22,84.76 ; P2.S1 40.9,101.37 ; P2.S1 39.68,100.15 ; P2.S1 39.68,102.59 ; J70.S2 112.66,103.59 ; J70.S2 111.02,101.95 ; J70.S2 111.02,105.23 ; 44.96,101.37 P1.S2 ; P1.S2 46.18,102.59 ; P1.S2 46.18,100.15 ; P2.S3 40.9,117.73 ; P2.S3 39.68,116.51 ; P2.S3 38.46,117.73 ; 126.07,4.05 BH7.1 129.33,7.31 ; 46.18,116.51 P1.S4 44.96,117.73
  L4_INT_2 w0.508: 114.29,3.95 114.29,3.95 J58.S3 113.3,1.95 113.27,1.92 ; 124.19,3.83 124.19,3.82 J58.S4 125.18,1.95 125.21,1.92
  L4_INT_2 w0.889: 124.95,5.95 J58.S2 124.19,7.17 ; 113.53,5.95 J58.S1 114.29,7.17 ; 18.59,4.05 BH6.1 15.32,7.31 ; 126.07,4.05 BH7.1 129.33,7.31
  BOTTOM w0.508: 125.21,1.92 125.18,1.95 J58.S4 124.19,3.82 124.19,3.83 ; 114.29,3.95 114.29,3.95 J58.S3 113.42,1.95 113.4,1.92 ; P2.S4 22.89,116.5 21.12,114.72 C388.1
  BOTTOM w0.889: 124.19,7.17 J58.S2 124.95,5.95 ; 61.75,117.73 P1.S3 ; P1.S3 62.97,118.95 ; P1.S3 64.19,117.73 ; 114.29,7.17 J58.S1 113.53,5.95
  vias: v2(41.51,117.87) v5(67.14,118.84) v5(67.09,117.82) v5(84.29,119.04) v5(85.33,119.07) v5(88.3,120.11) v5(89.14,120.13) v5(95.67,118.99) v5(95.62,118.18) v5(97.72,118.99)
V1V0_GND: length 25.6
  TOP w0.137: v2(128,48.66) C128.2 ; R56.1 v2(126.35,50.46)
  TOP w0.254: v2(127.11,40.91) 126.63,40.91 126.4,41.14 R887.1 126.35,42.03 C126.2
  TOP w0.381: C128.2 C127.2
  TOP w0.406: U557.B5 v3(121.75,43.76)
  BOTTOM w0.381: C1472.2 126.35,46.46 125.63,45.74 C36.2 122.79,44.8 v3(121.75,43.76) 124.27,43.76 v2(127.11,40.91) ; C1472.2 127.11,46.5 128,47.39 v2(128,48.66) 127.45,48.66 126.35,49.76 v2(126.35,50.46) ; C1472.2 R15.2
V1V0_MS: length 5.3
  TOP w0.254: U557.B3 v3(121.75,46.16)
  L3_INT_1 w0.381: v3(121.75,46.16) 122.4,46.16 v5(124.52,48.28)
  BOTTOM w0.381: v5(124.52,48.28) 124.7,48.1 124.88,48.1 R15.1
V1V0_RT: length 5.4
  TOP w0.254: U557.A3 123.72,47.33 123.72,48.27 124.72,49.27 124.93,49.27 R56.2
V1V0_SVIN: length 4.1
  TOP w0.406: U557.C1 v3(120.95,46.96)
  BOTTOM w0.381: R13.2 121.89,47.9 v3(120.95,46.96)
  BOTTOM w0.508: R13.2 122.14,48.15 122.79,47.49 C36.1
V1V0_TRK: length 5
  TOP w0.381: U557.B4 121.35,44.95 v3(121.73,44.57)
  L3_INT_1 w0.381: v2(124.61,46.5) 122.68,44.57 v3(121.73,44.57)
  BOTTOM w0.137: C1472.1 v2(124.61,46.5)
V3V3_BIAS: length 2.6
  TOP w0.381: C1342.2 116.04,71.2 v4(116.04,70.58) 116.23,70.38 116.8,70.38 U560.1
  BOTTOM w0.381: R904.2 116.04,71.21 v4(116.04,70.58)
V3V3_COMP: length 3.2
  TOP w0.254: R905.1 118.24,73.29 C1471.1 118.25,72.71 118.48,72.48 U560.22
V5V0_FB: length 3.6
  TOP w0.254: C19.1 115.93,82.82 115.92,82.83 114.93,82.83 U1.13 ; C19.1 116.72,82.85 R886.1 ; C19.1 116.7,81.88 R7.1
V5V0_INTVCC: length 1.8
  TOP w0.254: C1333.2 113.77,86.25 U1.2
V5V0_RT: length 2
  TOP w0.254: R11.2 115.05,86.06 114.59,85.6 114.53,85.6 114.27,85.35 U1.1
V5V0_SS: length 2.1
  TOP w0.254: C18.2 116.25,84.6 115.48,83.83 U1.15
VBAT: length 29.6
  TOP w0.137: v2(28.24,73.93) 27.55,73.93 27.55,73.93 C1253.1
  L3_INT_1 w0.107: BT3.1 BT3.2
  BOTTOM w0.137: v2(28.24,73.93) U523.19 25.92,73.93 25.39,73.4 22.08,73.4 20.85,72.16 16.1,72.16 14.08,70.15 BT3.1
VBUS: length 3.2
  TOP w0.305: U536.8 123.77,11.27 124.32,11.82 R849.1 R850.1
VCC_USB1_PWR: length 67.3
  TOP w0.254: U40.C2 U40.D2 U40.D1
  TOP w0.381: v3(72.63,51.79) 72.23,51.4 U14.E7
  L3_INT_1 w0.107: v3(72.63,51.79) 72.72,51.79 73.08,52.15 73.49,52.15 73.87,52.53 73.87,52.79 74.18,53.1
  L3_INT_1 w0.381: 74.18,53.1 74.66,53.1 76.69,55.12 76.69,55.7 78.61,57.63 80.38,57.63 80.4,57.65 80.75,57.65 81.42,58.32 82.84,58.32 v4(83.24,57.91)
  BOTTOM w0.381: v4(83.24,57.91) 83.83,58.5 83.83,60.62 83.86,60.65 83.86,61.68 85.58,63.41 85.58,64.35 97.75,76.52 97.75,81.07 100.04,83.35 100.04,88.27 103.58,91.81 110.04,91.81 112,93.77 112.38,93.77 v5(112.43,93.72)
  vias: v5(114.92,94.89)
VCC_USB2_PWR: length 53.9
  TOP w0.254: U550.D1 U550.D2 U550.C2
  TOP w0.381: v2(80.78,53.99) R471.2 R255.1
  BOTTOM w0.381: v2(80.78,53.99) 82.09,53.99 82.47,54.38 82.47,54.74 83.25,55.52 83.25,57 82.67,57.58 82.67,58.46 83.32,59.11 83.32,61.87 85.08,63.62 85.08,64.78 96.47,76.17 96.47,81.26 99.25,84.04 99.25,88.42 104.3,93.46 104.61,93.46
  BOTTOM w0.508: 104.61,93.46 105.24,93.46 v5(105.29,93.41)
  vias: v5(108.21,94.58)
VDD_CLKOUT: length 3.5
  TOP w0.254: U50.33 30.28,63.84 v2(30.29,63.83) ; U50.18 v2(23.3,63.84) ; U50.15 23.37,65.34 v2(23.37,65.34) ; U50.25 v2(26.58,61.68) ; U50.28 v2(28.08,61.68)
VDD_FB: length 14
  TOP w0.254: C122.2 125.33,44.57 R59.1 122.51,44.52 U557.A5 ; C122.2 R55.2 ; C122.2 124.34,45.36 v2(124.14,45.15)
  BOTTOM w0.254: J8.1 129.69,46.79 128.55,46.79 126.91,45.15 v2(124.14,45.15)
VDD_FDIVH: length 43
  TOP w0.137: v2(124.81,47.1) 125.75,47.1 R55.1 C122.1 R894.1 ; R52.2 109.46,34.43 v2(109.64,34.26)
  L3_INT_1 w0.107: v2(126.17,29.23) 125.27,30.14 124.88,30.14 124.48,30.53 124.48,34.21 123.8,34.89 123.8,43.19 125.02,44.4 125.02,46.89 v2(124.81,47.1)
  BOTTOM w0.137: v2(126.17,29.23) 125.52,29.89 119.65,29.89 118.89,30.65 113.24,30.65 v2(109.64,34.26)
VDD_FDIVL: length 4.4
  TOP w0.254: R64.1 R60.2 R896.1 127.06,44.52 R59.2 126.35,44.47 R62.2
VDD_INTVCC: length 2.6
  TOP w0.254: C125.1 122.52,42.18 U557.B6
VDD_ITH: length 5.4
  TOP w0.137: C127.1 R67.1
  TOP w0.254: U557.A4 124.03,46.84 124.03,47.01 124.66,47.64 R67.1
VDD_LP: length 51.4
  TOP w0.137: v2(90.29,57.25) 90.29,57.33 90.78,56.85 91.03,56.85 R144.1 ; R560.2 77.92,57.13 77.92,57.02 v4(78.38,56.56)
  TOP w0.381: U14.G12 70.63,47.4 v1(71.03,47.79)
  L3_INT_1 w0.107: v4(78.38,56.56) 78.95,57.12 81.41,57.12 81.59,57.3 82.99,57.3 83.03,57.25 88.24,57.25 88.24,57.25 v2(90.29,57.25) 90.81,57.25 91.45,56.6 92.24,56.6 92.39,56.75 97.96,56.75 98.63,56.08 99.98,56.08 100.83,56.93 101.74,56.93 v2(102.08,56.59)
  L4_INT_2 w0.107: v2(102.08,56.59) 102.72,57.23 102.72,59.68 J9.1
  L4_INT_2 w0.178: v1(71.03,47.79) 71.47,48.24 72.09,48.24 72.23,48.1 72.23,47.57 72.4,47.39 74.63,47.39
  L4_INT_2 w0.381: v4(78.38,56.56) 78.38,55.99 79.66,54.71 79.66,50.23 79.2,49.77 79.2,49.77 79.09,49.66 79.09,47.98 78.5,47.39 74.63,47.39
VDD_SEL: length 4.4
  TOP w0.254: J8.2 130.54,44.99 129.81,44.26 129.81,44.24 129.05,43.47 128.79,43.47 R60.1
VDD_SI5332: length 2.7
  TOP w0.254: v4(27.59,68.61) 27.58,68.6 U50.4 ; v4(28.7,68.73) 29.08,68.34 U50.1 ; U50.9 25.08,68.36 v4(25.33,68.61)
VDD_VBUS: length 10
  TOP w0.137: R899.1 v2(129.14,47.52) 129.14,48.63 127.12,50.66 127.12,54.63 126.74,55.01 U558.8
VDD_VOUTM: length 4.1
  TOP w0.254: C126.1 R62.1 124.76,43.65 124.46,43.36 U557.A6
VDDO7: length 0.5
  TOP w0.254: U50.40 29.59,67.78 v4(29.67,67.85)
32KHZ_LP_RTC: length 94.4
  TOP w0.137: v2(24.07,72.93) 22.76,72.93 R25.2 ; U24.3 90.18,58.64 90.23,58.7 90.24,58.7 v2(90.53,59)
  L3_INT_1 w0.107: v2(24.07,72.93) 24.88,72.12 29.65,72.12 31.86,69.92 31.86,69.39 32.65,68.6 35.33,68.6 36.19,67.74 57.5,67.74 59.66,65.57 61.76,65.57 63.58,67.39 64.92,67.39 65.27,67.74 67.18,67.74 67.72,67.19 74.01,67.19 74.76,67.95 84.81,67.95 86.59,69.72 91.81,69.72 92.23,70.14 v2(93.7,70.14)
  L4_INT_2 w0.107: v2(93.7,70.14) 93.7,69.58 92.49,68.37 92.03,68.37 90.31,66.65 90.31,62.29 91.09,61.5 91.09,59.55 v2(90.53,59)
  BOTTOM w0.137: v2(90.53,59) 90.09,58.55 89.72,58.55 R33.1
32KHZ_RTC: length 2.9
  TOP w0.137: v2(89.68,60.49) 89.68,60.22 89.4,59.94 U24.1
  BOTTOM w0.137: R36.1 88.74,60.09 R953.2 89.28,60.09 v2(89.68,60.49)
BRD_REV0: length 13.3
  TOP w0.137: v2(84.62,41) 83.03,42.6 76.52,42.6 76.12,42.19 75.03,42.19 U14.B18
  BOTTOM w0.137: v2(84.62,41) 84.62,40.58 84.76,40.44 R817.1 R816.1
BRD_REV1: length 15.1
  TOP w0.137: U14.D17 v3(73.42,43)
  BOTTOM w0.137: v3(73.42,43) 73.85,42.57 75.22,42.57 75.58,42.21 76.01,42.21 77.1,41.13 81.27,41.13 81.58,41.44 81.58,41.77 81.97,42.16 85.14,42.16 R815.1 R818.1
BUFF_I2C1_SCL: length 8.1
  TOP w0.137: U538.2 107.71,63.82 v2(107.2,64.33)
  BOTTOM w0.137: R856.2 107.43,63.68 107.2,63.91 v2(107.2,64.33) 108.3,64.33 109.49,65.52 J65.3
BUFF_I2C1_SDA: length 8.2
  TOP w0.137: U538.7 106.13,63.82 v2(106.54,64.23) 106.77,64.46 106.77,64.89 106.91,65.03 106.91,66.03 105.37,67.57 J65.1
  BOTTOM w0.137: v2(106.54,64.23) R855.2
C_USB1_TX_N: length 29.9
  BOTTOM w0.132: J70.8 106.77,106.09 arc(106.89,106.29) 106.91,106.52 arc(106.85,106.69) 106.75,106.84 arc(106.44,107.52) 106.59,108.26 arc(107.79,109.03) 109.1,108.45 arc(109.32,108.15) 109.52,107.83 arc(110.73,106.39) 112.32,105.41 arc(112.76,105.04) 112.89,104.49 arc(112.92,103.83) 113.13,103.2 arc(113.17,102.91) 113.06,102.65 arc(111.66,101.54) 109.93,101.08 arc(109.49,101.02) 109.07,100.87 arc(107.68,100.41) 106.23,100.3 arc(105.55,100.3) 104.87,100.25 arc(104.2,100.09) 103.59,99.76 arc(103.17,99.43) 102.78,99.07 102.09,98.36 arc(101.67,97.71) 101.52,96.95 101.52,96.82 arc(101.53,96.77) 101.56,96.73 101.61,96.68 arc(101.64,96.64) 101.65,96.59 U553.10 U553.1 101.65,94.4 arc(101.66,94.31) C463.1
C_USB1_TX_P: length 30
  BOTTOM w0.132: J70.9 107.72,105.77 arc(107.65,105.78) 107.6,105.82 107.46,105.96 arc(107.26,106.23) 107.15,106.56 arc(107.08,106.8) 106.94,107 arc(106.69,107.55) 106.81,108.14 arc(107.81,108.78) 108.9,108.3 arc(109.12,108.01) 109.31,107.7 arc(110.57,106.21) 112.23,105.18 arc(112.55,104.91) 112.64,104.51 arc(112.68,103.78) 112.91,103.09 arc(112.93,102.94) 112.87,102.8 arc(111.55,101.76) 109.92,101.33 arc(109.43,101.26) 108.97,101.09 arc(107.64,100.66) 106.24,100.54 arc(105.54,100.55) 104.84,100.5 arc(104.11,100.32) 103.45,99.96 arc(103.01,99.62) 102.61,99.24 101.91,98.53 arc(101.44,97.8) 101.27,96.95 101.27,96.82 arc(101.26,96.77) 101.24,96.73 101.18,96.68 arc(101.15,96.64) 101.15,96.59 U553.9 U553.2 101.15,94.65 arc(101.1,94.43) C464.1
C_USB2_TX_N: length 14.1
  BOTTOM w0.132: J70.17 107.19,102.57 arc(107.29,102.53) 107.33,102.44 107.33,101.97 arc(107.2,101.66) 106.88,101.53 104.49,101.53 arc(103.78,101.38) 103.18,100.98 100.14,97.95 arc(99.87,97.53) 99.77,97.05 99.77,96.82 arc(99.76,96.77) 99.73,96.73 99.68,96.68 arc(99.65,96.64) 99.65,96.59 U553.6 U553.5 99.65,94.58 arc(99.61,94.4) C1326.2
C_USB2_TX_P: length 14.1
  BOTTOM w0.132: J70.18 107.71,102.57 arc(107.61,102.53) 107.57,102.44 107.57,101.97 arc(107.37,101.48) 106.88,101.28 104.49,101.28 arc(103.88,101.16) 103.35,100.81 100.32,97.77 arc(100.1,97.44) 100.02,97.05 100.02,96.82 arc(100.03,96.77) 100.06,96.73 100.11,96.68 arc(100.14,96.64) 100.15,96.59 U553.7 U553.4 100.15,94.34 arc(100.16,94.29) C1325.2
CFG_DRAM_TYPE: length 12.3
  TOP w0.137: U14.C11 73.83,48.2 v3(74.23,48.59)
  BOTTOM w0.137: R228.1 85.26,47.45 75.75,47.45 74.6,48.59 v3(74.23,48.59)
CFG_ENG_USE0: length 2.5
  TOP w0.137: S1.10 v2(112.89,14.62)
  BOTTOM w0.137: R813.2 112.46,14.61 112.47,14.62 v2(112.89,14.62)
CFG_RCW_SRC0: length 2.2
  TOP w0.137: S1.1 v2(112.71,3.18)
  BOTTOM w0.137: R908.2 112.14,3.17 112.16,3.18 v2(112.71,3.18)
CFG_RCW_SRC1: length 2.3
  TOP w0.137: S1.2 v2(112.76,4.45)
  BOTTOM w0.137: v2(112.76,4.45) 112.16,4.45 112.14,4.44 R909.2
CFG_RCW_SRC2: length 2.2
  TOP w0.137: S1.3 v2(112.71,5.72)
  BOTTOM w0.137: v2(112.71,5.72) 112.16,5.72 112.14,5.71 R910.2
CFG_RCW_SRC3: length 2.1
  TOP w0.137: S1.4 v2(112.68,6.99)
  BOTTOM w0.137: R911.2 112.14,6.98 112.16,6.99 v2(112.68,6.99)
CFG_RCW_SRC4: length 2.3
  TOP w0.137: S1.5 v2(112.78,8.27)
  BOTTOM w0.137: R912.2 112.14,8.26 112.16,8.27 v2(112.78,8.27)
CFG_RCW_SRC5: length 3
  TOP w0.137: S1.6 112.46,9.54 112.63,9.37 v2(112.63,8.94)
  BOTTOM w0.137: R913.2 112.47,9.53 112.63,9.37 v2(112.63,8.94)
CFG_RCW_SRC6: length 2.2
  TOP w0.137: S1.7 v2(112.75,10.81)
  BOTTOM w0.137: R914.2 112.14,10.8 112.16,10.81 v2(112.75,10.81)
CFG_RCW_SRC7: length 2.3
  TOP w0.137: S1.8 v2(112.77,12.08)
  BOTTOM w0.137: v2(112.77,12.08) 112.16,12.08 112.14,12.07 R915.2
CFG_RCW_SRC8: length 2.4
  TOP w0.137: S1.9 v2(112.83,13.35)
  BOTTOM w0.137: R812.2 112.4,13.34 112.41,13.35 v2(112.83,13.35)
CLK_32KHZ: length 104.3
  TOP w0.137: R739.2 20.09,78.31 20.08,78.33 v2(19.65,78.33) 19.95,78.03 19.95,74.94 R25.1
  L3_INT_1 w0.107: v2(19.65,78.33) 19.94,78.04 19.94,78.02 19.95,78.01 19.95,75.63 23.86,71.72 29.08,71.72 30.74,70.06 30.74,69.59 32,68.33 35.26,68.33 36.09,67.5 57.29,67.5 59.55,65.25 61.96,65.25 63.76,67.04 65.09,67.04 65.56,67.51 67.08,67.51 67.63,66.96 74.29,66.96 74.97,67.63 85.29,67.63 86.79,69.14 92.22,69.14 92.27,69.18 v2(92.68,69.18)
  BOTTOM w0.137: v2(19.65,78.33) 19.65,79.33 18.7,80.28 U523.7 ; v2(92.68,69.18) 92.68,68.29 90.29,65.9 90.29,63.05 88.08,60.85 88.08,60.46 R953.1
CLK_RTC: length 39.9
  TOP w0.137: U24.6 90.89,59.94 v2(90.64,60.19) ; v3(71.82,43) U14.F17
  L3_INT_1 w0.107: v2(82.08,60.31) 84.12,60.31 84.29,60.14 86.15,60.14 86.77,60.75 87.97,60.75 88.22,61.01 89.82,61.01 v2(90.64,60.19)
  L4_INT_2 w0.107: v2(81.06,55.86) 81.06,55.34 81.41,54.99 81.41,50.8 79.93,49.31 79.93,47.39 79.59,47.05 79.59,43.46 78.07,41.94 75.67,41.94 75.04,42.58 73.26,42.58 73.24,42.55 72.27,42.55 v3(71.82,43)
  BOTTOM w0.137: v2(90.64,60.19) 91.09,60.64 R143.2 ; v2(81.06,55.86) 80.76,56.16 80.76,56.33 80.76,56.34 80.76,56.45 80.75,56.46 80.75,57.72 81.54,58.52 81.93,58.52 82.08,58.67 v2(82.08,60.31)
CLKGEN_OUT2_N: length 1.2
  TOP w0.124: R792.1 24.6,61.49 24.6,61.84 24.58,61.85 U50.21
CLKGEN_OUT2_P: length 1.3
  TOP w0.124: R791.1 24.92,61.43 24.92,61.69 25.08,61.85 U50.22
CLKGEN_OUT3_N: length 5.2
  TOP w0.124: R788.1 27.63,59.08 26.41,59.08 26,59.49 26,60.95 25.67,61.27 25.67,61.76 25.58,61.85 U50.23
CLKGEN_OUT3_P: length 5.1
  TOP w0.124: R787.1 27.56,59.4 26.54,59.4 26.32,59.62 26.32,59.86 26.44,59.98 26.57,59.98 26.69,60.1 26.69,60.35 26.57,60.48 26.44,60.48 26.32,60.6 26.32,61.08 25.99,61.4 25.99,61.76 26.08,61.85 U50.24
CLKGEN_OUT4_N: length 8.2
  TOP w0.124: R790.1 32.6,61.98 31.43,61.98 31.26,61.81 31.26,61.38 30.28,60.39 27.96,60.39 27.17,61.18 27.17,61.76 27.08,61.85 U50.26
CLKGEN_OUT4_P: length 8.1
  TOP w0.124: R789.1 32.48,62.3 32.15,62.3 32.03,62.43 32.03,62.48 31.9,62.61 31.66,62.61 31.53,62.48 31.53,62.43 31.41,62.3 31.15,62.3 30.94,62.1 30.94,61.51 30.14,60.71 28.1,60.71 27.49,61.31 27.49,61.76 27.58,61.85 U50.27
CLKGEN_OUT5_N: length 7
  TOP w0.124: R786.1 32.63,63.64 32.34,63.92 32.04,63.92 30.46,62.34 30.46,61.68 29.81,61.04 29.01,61.04 28.66,61.38 28.66,62.25 U50.29
CLKGEN_OUT5_P: length 6.9
  TOP w0.124: R785.1 32.6,64.53 32.31,64.24 31.91,64.24 31.83,64.16 31.65,64.16 31.57,64.24 31.4,64.24 31.22,64.06 31.22,63.89 31.3,63.81 31.3,63.64 30.14,62.48 30.14,61.82 29.68,61.36 29.14,61.36 28.98,61.51 28.98,62.23 U50.30
CLKGEN_OUT6_N: length 3.4
  TOP w0.124: R784.1 31.39,65.63 31.08,65.93 30.91,65.93 30.78,65.81 30.78,64.74 30.47,64.43 30.16,64.43 30.07,64.34 U50.34
CLKGEN_OUT6_P: length 3.3
  TOP w0.124: U50.35 30.07,64.84 30.16,64.75 30.34,64.75 30.46,64.88 30.46,65.94 30.77,66.25 31.08,66.25 31.32,66.49 R783.1
CLKGEN_OUT7: length 2.6
  TOP w0.137: U50.39 29.69,66.84 30.78,67.93 31.19,67.93 R781.1
CLKGEN_OUT8: length 2.4
  TOP w0.137: R782.1 31.01,67.36 30,66.34 U50.38
CONN_SPI_CLK: length 19.8
  TOP w0.137: J66.4 74.03,91.53 78.55,96.05 79.69,96.05 81.04,97.4 81.04,102.06 80.9,102.2 79.84,102.2 79.69,102.05 U539.2
CONN_SPI_CS1_B: length 18.3
  TOP w0.137: U36.2 82.78,102.07 82.92,102.2 83.92,102.2 84.14,101.99 84.14,94.21 79.11,89.18 79.11,88.79
CONN_SPI_CS2_B: length 18
  TOP w0.137: J66.7 81.65,90.52 87.62,96.49 87.62,101.36 87.18,101.8 86.17,101.8 85.78,101.41 U540.2
CONN_SPI_CS3_B: length 19
  TOP w0.137: U540.3 85.28,101.93 85.61,102.25 87.39,102.25 88.15,101.49 88.15,96.41 85.25,93.51 85.25,89.86 J66.8
CONN_SPI_MISO: length 19.4
  TOP w0.137: J66.3 71.49,90.62 77.99,97.12 77.99,103.79 77.82,103.95 77.05,103.95 R941.2
CONN_SPI_MOSI: length 17.6
  TOP w0.137: J66.2 68.95,90.62 75.04,96.72 75.04,101.58 74.91,101.72 74.05,101.72 73.89,101.56 U35.2
CP2102_SIN: length 6.5
  TOP w0.137: U536.18 117.64,11.77 115.68,13.73 J72.2
CP2102_SOUT: length 2.5
  TOP w0.137: U536.17 119.28,12.27 R837.2 R841.2
CPU_ASLEEP: length 37.9
  TOP w0.137: v3(72.63,50.19) 72.62,50.19 U14.E9 ; v2(93.65,50.34) 93.43,50.12 93.43,49.51 Q4.2 93.44,48.79 93.16,48.51 R192.1
  L3_INT_1 w0.107: v2(93.46,57.24) 93.05,57.24 92.92,57.11 91.47,57.11 90.92,57.66 89.82,57.66 88.85,58.63 83.44,58.63 82.71,59.36 81.13,59.36 79.77,58 78.02,58 75.01,54.99 75.01,54.44 74.78,54.21 74.5,54.21 74.21,53.92 74.21,53.64 73.99,53.41 73.74,53.41 72.98,52.66 72.98,52.45 72.77,52.24 72.56,52.24 72.27,51.94 72.27,50.55 v3(72.63,50.19)
  L4_INT_2 w0.107: v2(93.65,50.34) 93.65,55.46 93.66,55.47 93.66,55.8 93.65,55.81 93.65,56.36 93.46,56.55 v2(93.46,57.24)
CPU_CKSTP_OUT_B: length 18.2
  TOP w0.137: v3(71.02,44.59) 70.62,44.99 U14.G15
  BOTTOM w0.137: v3(71.02,44.59) 71.02,44.44 71.43,44.03 71.43,43.65 71.67,43.42 71.98,43.42 72.22,43.67 72.22,44.11 73.17,45.06 75.2,45.06 76.97,43.29 81.66,43.29 82.66,44.29 84.65,44.29 R187.1
CPU_CLKOUT: length 23.6
  TOP w0.137: TP126.1 v2(90.64,45.23) 89.37,46.5 82.19,46.5 v2(81.89,46.2) ; v3(71.02,43.8) U14.G16
  L3_INT_1 w0.107: v2(81.89,46.2) 81.49,46.36 80.39,46.36 79.3,45.27 71.19,45.27 70.67,44.74 70.67,44.15 v3(71.02,43.8)
CPU_EVT0_B: length 13.6
  TOP w0.137: v3(72.63,49.39) 72.62,49.39 U14.E10
  BOTTOM w0.137: R167.2 83.86,51.18 83.69,51.01 83.34,51.01 83.17,51.18 82.26,51.18 81.71,50.64 76.84,50.64 75.97,49.77 73,49.77 v3(72.63,49.39)
CPU_EVT1_B: length 14.6
  TOP w0.381: U14.E13 72.23,46.6 v3(72.63,46.99)
  BOTTOM w0.137: v3(72.63,46.99) 73,46.62 83.56,46.62 83.84,46.34 85.69,46.34 R168.2
CPU_EVT2_B: length 9.2
  TOP w0.137: U14.E8 72.62,50.99 v3(72.63,50.99)
  BOTTOM w0.137: v3(72.63,50.99) 73.03,50.59 75.24,50.59 79.02,54.37 R169.2
CPU_EVT3_B: length 16
  TOP w0.381: U14.E12 72.23,47.4 v3(72.63,47.79)
  BOTTOM w0.137: v3(72.63,47.79) 73.02,47.4 74.5,47.4 74.98,46.92 83.63,46.92 83.89,46.66 86.38,46.66 R170.2
CPU_EVT4_B: length 18
  TOP w0.137: v3(72.63,48.59) 72.23,48.2 U14.E11
  BOTTOM w0.137: R161.2 87.75,46.92 84.02,46.92 83.76,47.18 75.43,47.18 74.4,48.22 73,48.22 v3(72.63,48.59)
CPU_HRESET_B: length 82.4
  TOP w0.137: v3(71.83,50.99) 71.43,50.6 U14.F8
  L3_INT_1 w0.107: v2(81.78,55.23) 83.01,55.23 83.65,55.87 87.67,55.87 88.88,54.66 93.57,54.66 93.73,54.82 93.89,54.82 94.07,55 95.1,55 95.78,55.68 100.24,55.68 101.04,56.47 101.42,56.47 101.97,55.91 102.96,55.91 104.4,54.48 106.75,54.48 110.74,50.49 112.66,50.49 115.45,47.69 115.45,41.1 115.99,40.57 115.99,32.54 v2(119.07,29.45) 119.36,29.16 119.36,26.12 v2(119,25.76)
  BOTTOM w0.137: U114.2 v2(119,25.76) ; v2(81.78,55.23) 81.27,55.23 81.07,55.44 78.63,55.44 77.46,54.26 77.46,53.8 75.92,52.27 74.97,52.27 74.65,51.95 74.65,51.69 74.35,51.39 72.4,51.39 72.01,50.99 v3(71.83,50.99) ; U533.4 122.23,29.18 R825.2 123.01,29.62 119.25,29.62 v2(119.07,29.45)
CPU_ID: length 19.5
  TOP w0.137: v2(51.61,59.5) 51.19,59.5 50.69,59.99 R819.1 ; U14.AG3 v2(54.22,55) ; v3(63.82,54.2) 63.82,54.19 U14.R4
  L3_INT_1 w0.107: v3(63.82,54.2) 63.41,54.61 55.67,54.61 55.44,54.84 55.44,55.12 55.18,55.38 54.61,55.38 v2(54.22,55)
  L4_INT_2 w0.107: v2(54.22,55) 53.68,55 51.61,57.07 v2(51.61,59.5)
CPU_JTAG_BSR_VSEL: length 18
  TOP w0.137: v2(81.49,44.93) 82.38,44.93 82.39,44.92 R185.1 R172.2 ; v3(68.62,41.4) U14.J19
  L3_INT_1 w0.107: v3(68.62,41.4) 68.98,41.75 69.52,41.75 69.84,42.07 69.84,42.36 70.06,42.58 71.91,42.58 72.18,42.85 72.18,43.86 72.48,44.16 80.16,44.16 80.93,44.93 v2(81.49,44.93)
CPU_JTAG_RST_B: length 161.3
  TOP w0.137: v2(20.53,85.25) 20.64,85.36 J15.10
  L3_INT_1 w0.107: v2(105.76,71.91) 105.47,72.2 99.62,72.2 99.61,72.21 94.61,72.21 94.15,71.75 85.44,71.75 83.01,69.32 76.15,69.32 75.57,69.9 71.68,69.9 71.2,69.43 71.18,69.43 70.5,68.75 68.8,68.75 68.36,69.18 64.47,69.18 64.22,68.94 62.53,68.94 62.34,69.13 59.25,69.13 57.01,71.37 52.54,71.37 51.71,72.19 44.49,72.19 43.99,72.69 39.11,72.69 36.67,75.13 34.45,75.13 29,80.58 28.06,80.58 25.05,83.6 23.87,83.6 22.22,85.25 v2(20.53,85.25) ; v2(115.22,22.21) 115.22,23.18 115.07,23.33 v2(115.07,31.29)
  L4_INT_2 w0.107: v2(105.76,71.91) 105.76,67.43 106.04,67.14 106.04,66.24 106.06,66.23 106.06,64.13 107.52,62.67 107.52,57.33 106.16,55.98 105.17,55.98 104.74,55.54 104.74,51.71 103.29,50.26 102.49,50.26 101.29,49.06 101.29,46.49 103.33,44.44 103.44,44.44 111.56,36.32 111.56,34.8 v2(115.07,31.29)
  BOTTOM w0.137: U55.1 119.51,22.33 119.49,22.34 R303.2 118.24,21.83 115.6,21.83 v2(115.22,22.21)
CPU_JTAG_VTREF: length 3
  TOP w0.137: R186.2 24.87,79.32 24.87,79.77 25.37,80.28 J15.1
CPU_LVDD: length 2.8
  TOP w0.381: v1(61.42,51.79) U14.V7 61.83,51.4 v1(62.22,51.79) U14.U7 63.02,51.79 v1(63.03,51.79) U14.T7
  vias: v2(54.82,58.71) v2(55.34,58.35) v2(56.01,58.47)
CPU_PORESET_B: length 87.5
  TOP w0.137: U14.F9 71.43,49.8 v3(71.83,50.19) ; v2(120.33,24.38) 119.7,24.38 118.99,23.67 118.45,23.67 118.1,24.03 TP142.1
  L3_INT_1 w0.107: v3(71.83,50.19) 71.47,50.55 71.47,51.94 71.68,52.15 71.89,52.15 72.27,52.53 72.27,52.74 72.48,52.95 72.72,52.95 73.44,53.68 73.44,53.95 73.7,54.21 73.99,54.21 74.21,54.44 74.21,54.72 74.46,54.98 74.67,54.98 77.94,58.26 79.66,58.26 80.99,59.59 83.58,59.59 84.15,59.02 85.26,59.02 85.47,59.23 88.64,59.23 89.98,57.89 91.02,57.89 91.45,57.46 92.94,57.46 92.96,57.48 93.09,57.48 93.31,57.7 95.51,57.7 95.93,57.27 102.44,57.27 102.46,57.25 102.56,57.25 103.94,55.87 106.87,55.87 111.65,51.09 113.68,51.09 114.36,50.41 114.36,49.12 115.84,47.64 115.84,42.01 117.25,40.6 117.25,35.48 118.36,34.38 118.36,30.75 120.33,28.78 v2(120.33,24.38)
  BOTTOM w0.137: U55.4 122.25,24.1 121.98,24.38 v2(120.33,24.38)
